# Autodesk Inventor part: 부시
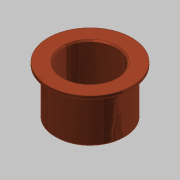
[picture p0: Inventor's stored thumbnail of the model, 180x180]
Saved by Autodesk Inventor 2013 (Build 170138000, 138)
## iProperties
Created: 2015-10
Part Number: 부시
Document SubType Name: Modeling
Designer: mdu
Density: 7.86 g/cm^3
Material: 강철, 연강
Mass: 246.238 g
Surface Area: 128.147 cm^2
Volume: 31.328 cm^3
Author: mdu
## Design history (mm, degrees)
sketch "스케치1"
  geometry: C1 r 31 at (0, 0) reference; C2 r 25 at (0, 0) reference; C3 r 30 at (0, 0) reference; 1 further point
  node "참조1"
  node "참조2"
  node "참조4"
extrude "돌출1" new body sketch "스케치1" distance "d0" = 3; taper "d1" = 0 deg
extrude "돌출2" join sketch "스케치1" distance "d2" = 35; taper "d3" = 0 deg
chamfer "모따기1" distance "d6" = 1; stored, may be unused: second distance "d7" = 2, angle "d8" = 45 deg
sketch "스케치3"
  geometry: C1 r 19 at (0, 0); 1 further point
  constraints: 1 centre point, 1 coincident
  dimensions: "d13" = 38 diameter of C1
extrude "돌출4" cut sketch "스케치3" stored distance "d14" = 10; taper "d15" = 0 deg
chamfer "모따기3" distance "d16" = 1; stored, may be unused: second distance "d17" = 2, angle "d18" = 45 deg
node "솔리드1"
